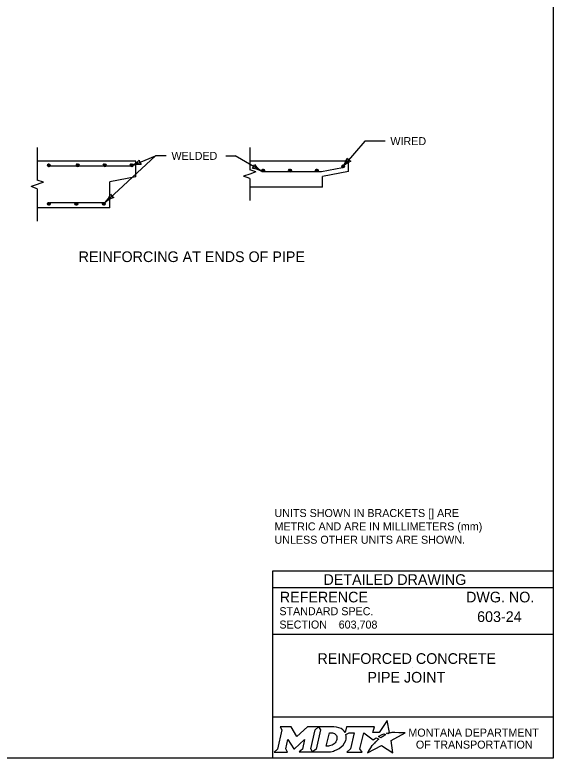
# Model space of a CAD drawing. Extents: x 49991.4 to 50021, y 49987.6 to 50011.4.
# Drawn here: x 50012.72 to 50016.75, y 49987.8 to 49993.37 of the extents above; entities that cross this region are included whole.
import ezdxf

# ---------------------------------------------------------------- set-up
doc = ezdxf.new("R2010")
doc.units = 0
for name, color, linetype in [('Default', 7, 'Continuous'), ('Level 1', 7, 'Continuous'), ('Level 2', 7, 'Continuous'), ('Level 3', 7, 'Continuous'), ('Level 5', 7, 'Continuous'), ('Level 6', 7, 'Continuous')]:
    doc.layers.add(name, color=color, linetype=linetype)

msp = doc.modelspace()

# ---------------------------------------------------------------- linework, layer by layer
at = {"layer": 'Default'}
for points in [[(50015.5126, 49987.9811), (50015.5023, 49987.9867), (50015.5139, 49987.9895), (50015.5255, 49987.9915), (50015.5081, 49988.0816), (50015.4486, 49987.9903), (50015.4013, 49987.9896), (50015.4116, 49988.0337), (50015.2024, 49988.0338), (50015.1923, 49987.9913), (50015.1865, 49987.9996)], [(50014.7056, 49988.0338), (50014.7197, 49988.0104), (50014.6862, 49987.8671), (50014.6605, 49987.8446), (50014.7621, 49987.8446), (50014.7486, 49987.8674), (50014.7648, 49987.9375), (50014.8085, 49987.8685), (50014.8138, 49987.8685), (50014.8889, 49987.938), (50014.8725, 49987.8669), (50014.8478, 49987.8449), (50014.9494, 49987.8449), (50014.9356, 49987.8682), (50014.9688, 49988.0106)], [(50014.9688, 49988.0106), (50014.9941, 49988.0338), (50014.9117, 49988.0338), (50014.8321, 49987.9608), (50014.7876, 49988.0335), (50014.7056, 49988.0338)], [(50015.1077, 49988.0338), (50014.9941, 49988.0338), (50015.0088, 49988.0109), (50014.9749, 49987.8671), (50014.9494, 49987.8449), (50015.06, 49987.8449)], [(50015.1317, 49987.9471), (50015.1305, 49987.939), (50015.1273, 49987.9297), (50015.1231, 49987.9215), (50015.1175, 49987.914), (50015.111, 49987.9071), (50015.1031, 49987.9008), (50015.0948, 49987.8961), (50015.0857, 49987.8922), (50015.0766, 49987.8899), (50015.0674, 49987.889), (50015.0515, 49987.889), (50015.0751, 49987.989), (50015.0911, 49987.989), (50015.0987, 49987.9884), (50015.1063, 49987.9865), (50015.1129, 49987.9835), (50015.119, 49987.9793), (50015.1238, 49987.9743), (50015.1275, 49987.9683), (50015.1302, 49987.9621), (50015.1318, 49987.9547), (50015.1318, 49987.9517), (50015.1317, 49987.9471)], [(50015.1991, 49987.9747), (50015.2237, 49987.9878), (50015.2606, 49987.9878), (50015.232, 49987.8673), (50015.2045, 49987.8446), (50015.3207, 49987.8446), (50015.3037, 49987.8675), (50015.3319, 49987.9877), (50015.4032, 49987.936), (50015.4243, 49987.9511), (50015.444, 49987.9402)], [(50015.3882, 49987.8843), (50015.3729, 49987.8599), (50015.3682, 49987.8524), (50015.3624, 49987.8438), (50015.3601, 49987.8395), (50015.4654, 49987.8926), (50015.5493, 49987.8375), (50015.5362, 49987.9302), (50015.6431, 49987.9886), (50015.5938, 49987.9894), (50015.5637, 49987.9898), (50015.5429, 49987.9901), (50015.5361, 49987.9886), (50015.5312, 49987.9874), (50015.5228, 49987.9851), (50015.5126, 49987.9811)], [(50015.4622, 49987.9535), (50015.4598, 49987.9518), (50015.4415, 49987.9614), (50015.4518, 49987.9671), (50015.4559, 49987.9693), (50015.4645, 49987.9733), (50015.4702, 49987.9759), (50015.4781, 49987.9789), (50015.4854, 49987.9816), (50015.4972, 49987.9742), (50015.4932, 49987.9721), (50015.4886, 49987.9696), (50015.4844, 49987.9674), (50015.4794, 49987.9645), (50015.4775, 49987.9634), (50015.4748, 49987.9618), (50015.4723, 49987.9604), (50015.47, 49987.9588), (50015.4674, 49987.957), (50015.4647, 49987.9552), (50015.4622, 49987.9535)], [(50015.4021, 49987.9004), (50015.4021, 49987.9004)], [(50015.1057, 49987.8522), (50015.1141, 49987.8548), (50015.1271, 49987.8602), (50015.1475, 49987.8712)]]:
    msp.add_lwpolyline(points, dxfattribs=at)
for centre, radius, start, end in [((50015.1308, 49987.9554), 0.0709, 339.5329, 15.8582), ((50015.0868, 49987.9727), 0.1183, 300.9103, 339.1383)]:
    msp.add_arc(centre, radius, start, end, dxfattribs=at)
for centre, major_axis, ratio, start_param, end_param in [((50015.1056, 49987.9864), (0.0834, -0.0037), 0.568097, 0.61298, 1.570796), ((50015.1612, 49987.9937), (0.0361, -0.0295), 0.469099, 1.225588, 1.570796), ((50015.4329, 49987.9305), (-0.0112, -0.0097), 0.021651, 3.157348, 6.283185), ((50015.3952, 49987.8923), (-0.00694, -0.00806), 0.008222, 0, 3.137361), ((50015.4119, 49987.9106), (-0.0098, -0.0102), 0.016458, 3.141593, 6.279097), ((50015.0603, 49987.9932), (0, 0.1484), 0.987302, 3.139398, 3.456847)]:
    msp.add_ellipse(centre, major_axis=major_axis, ratio=ratio, start_param=start_param, end_param=end_param, dxfattribs=at)
at = {"layer": 'Level 1'}
for p, q in [((50013.6268, 49992.2718), (50012.8876, 49992.2718)), ((50013.5877, 49992.2327), (50012.9814, 49992.2327)), ((50012.9814, 49992.2327), (50012.9814, 49992.2327)), ((50013.1834, 49992.2327), (50013.1834, 49992.2327)), ((50013.3856, 49992.2327), (50013.3856, 49992.2327)), ((50013.5877, 49992.2327), (50013.5877, 49992.2327)), ((50013.6268, 49992.1537), (50013.6268, 49992.2718)), ((50015.2179, 49992.2718), (50014.4786, 49992.2718)), ((50015.0148, 49992.1928), (50015.1719, 49992.2243)), ((50015.2179, 49992.1936), (50015.2179, 49992.2718)), ((50014.5724, 49992.1928), (50014.5724, 49992.1928)), ((50014.5724, 49992.1928), (50015.0148, 49992.1928)), ((50014.7733, 49992.1928), (50014.7733, 49992.1928)), ((50014.9742, 49992.1928), (50014.9742, 49992.1928)), ((50015.2179, 49992.1936), (50015.0225, 49992.1545)), ((50013.6268, 49992.1537), (50013.4314, 49992.1147)), ((50013.4314, 49991.92), (50013.4314, 49992.1147)), ((50015.0225, 49992.0764), (50015.0225, 49992.1545)), ((50015.0225, 49992.0764), (50014.4786, 49992.0764)), ((50013.3923, 49991.9591), (50012.9814, 49991.9591)), ((50012.9814, 49991.9591), (50012.9814, 49991.9591)), ((50013.1868, 49991.9591), (50013.1868, 49991.9591)), ((50013.3923, 49991.9591), (50013.3923, 49991.9591)), ((50013.4314, 49991.92), (50012.8876, 49991.92))]:
    msp.add_line(p, q, dxfattribs=at)
msp.add_lwpolyline([(49999.3835, 49998.9992), (50016.7501, 49998.9992), (50016.7501, 49987.7988), (49999.3835, 49987.7988)], close=True, dxfattribs=at)
for points in [[(50012.9635, 49992.2387), (50012.9746, 49992.2497)], [(50012.9636, 49992.2404), (50012.9729, 49992.2497)], [(50012.9638, 49992.2372), (50012.9761, 49992.2495)], [(50012.9639, 49992.2424), (50012.9709, 49992.2493)], [(50012.9642, 49992.236), (50012.9773, 49992.2491)], [(50012.9647, 49992.2348), (50012.9785, 49992.2486)], [(50012.9653, 49992.2338), (50012.9795, 49992.248)], [(50012.9657, 49992.2458), (50012.9675, 49992.2476), (50012.9676, 49992.2477)], [(50012.966, 49992.2328), (50012.966, 49992.2329), (50012.9804, 49992.2473), (50012.9805, 49992.2473)], [(50012.9668, 49992.232), (50012.9668, 49992.232), (50012.9813, 49992.2465), (50012.9813, 49992.2465)], [(50012.9678, 49992.2313), (50012.982, 49992.2455)], [(50012.9688, 49992.2306), (50012.9827, 49992.2445)], [(50012.9699, 49992.23), (50012.9832, 49992.2434)], [(50012.9711, 49992.2297), (50012.9836, 49992.2422)], [(50012.9725, 49992.2293), (50012.9839, 49992.2408)], [(50012.9742, 49992.2293), (50012.9839, 49992.2392)], [(50012.9761, 49992.2296), (50012.9837, 49992.2372)], [(50012.9787, 49992.2306), (50012.9827, 49992.2346)], [(50013.1801, 49992.2395), (50013.1911, 49992.2505)], [(50013.1802, 49992.2411), (50013.1895, 49992.2505)], [(50013.1803, 49992.238), (50013.1926, 49992.2503)], [(50013.1805, 49992.2432), (50013.1874, 49992.2501)], [(50013.1807, 49992.2368), (50013.1938, 49992.2499)], [(50013.1813, 49992.2356), (50013.195, 49992.2494)], [(50013.1819, 49992.2346), (50013.196, 49992.2488)], [(50013.1822, 49992.2465), (50013.184, 49992.2484), (50013.1841, 49992.2485)], [(50013.1825, 49992.2336), (50013.1826, 49992.2336), (50013.197, 49992.2481), (50013.197, 49992.2481)], [(50013.1834, 49992.2328), (50013.1834, 49992.2328), (50013.1978, 49992.2472), (50013.1978, 49992.2472)], [(50013.1843, 49992.2321), (50013.1985, 49992.2463)], [(50013.1853, 49992.2314), (50013.1992, 49992.2453)], [(50013.1864, 49992.2308), (50013.1998, 49992.2442)], [(50013.1877, 49992.2304), (50013.2002, 49992.2429)], [(50013.1891, 49992.2301), (50013.2004, 49992.2415)], [(50013.1907, 49992.2301), (50013.2005, 49992.24)], [(50013.1926, 49992.2304), (50013.2002, 49992.238)], [(50013.1952, 49992.2314), (50013.1992, 49992.2354)], [(50013.3822, 49992.2395), (50013.3932, 49992.2505)], [(50013.3823, 49992.2411), (50013.3916, 49992.2505)], [(50013.3825, 49992.238), (50013.3947, 49992.2503)], [(50013.3826, 49992.2432), (50013.3896, 49992.2501)], [(50013.3829, 49992.2368), (50013.396, 49992.2499)], [(50013.3834, 49992.2356), (50013.3972, 49992.2494)], [(50013.384, 49992.2346), (50013.3982, 49992.2488)], [(50013.3843, 49992.2465), (50013.3861, 49992.2484), (50013.3863, 49992.2485)], [(50013.3846, 49992.2336), (50013.3847, 49992.2336), (50013.3991, 49992.2481), (50013.3992, 49992.2481)], [(50013.3855, 49992.2328), (50013.3855, 49992.2328), (50013.4, 49992.2472), (50013.4, 49992.2472)], [(50013.3864, 49992.2321), (50013.4007, 49992.2463)], [(50013.3875, 49992.2314), (50013.4014, 49992.2453)], [(50013.3886, 49992.2308), (50013.4019, 49992.2442)], [(50013.3898, 49992.2304), (50013.4023, 49992.2429)], [(50013.3912, 49992.2301), (50013.4025, 49992.2415)], [(50013.3929, 49992.2301), (50013.4026, 49992.24)], [(50013.3947, 49992.2304), (50013.4024, 49992.238)], [(50013.3974, 49992.2314), (50013.4014, 49992.2354)], [(50013.5843, 49992.2395), (50013.5953, 49992.2505)], [(50013.5844, 49992.2411), (50013.5937, 49992.2505)], [(50013.5845, 49992.238), (50013.5968, 49992.2503)], [(50013.5847, 49992.2432), (50013.5916, 49992.2501)], [(50013.5849, 49992.2368), (50013.5981, 49992.2499)], [(50013.5855, 49992.2356), (50013.5992, 49992.2494)], [(50013.5861, 49992.2346), (50013.6002, 49992.2488)], [(50013.5864, 49992.2465), (50013.5882, 49992.2484), (50013.5884, 49992.2485)], [(50013.5867, 49992.2336), (50013.5868, 49992.2336), (50013.6012, 49992.2481), (50013.6013, 49992.2481)], [(50013.5876, 49992.2328), (50013.5876, 49992.2328), (50013.602, 49992.2472), (50013.602, 49992.2472)], [(50013.5885, 49992.2321), (50013.6027, 49992.2463)], [(50013.5895, 49992.2314), (50013.6034, 49992.2453)], [(50013.5906, 49992.2308), (50013.604, 49992.2442)], [(50013.5919, 49992.2304), (50013.6044, 49992.2429)], [(50013.5933, 49992.2301), (50013.6046, 49992.2415)], [(50013.5949, 49992.2301), (50013.6047, 49992.24)], [(50013.5968, 49992.2304), (50013.6045, 49992.238)], [(50013.5995, 49992.2314), (50013.6034, 49992.2354)], [(50015.1686, 49992.2327), (50015.1779, 49992.2421)], [(50015.1686, 49992.2311), (50015.1796, 49992.2421)], [(50015.1688, 49992.2296), (50015.1811, 49992.2418)], [(50015.169, 49992.2347), (50015.1759, 49992.2417)], [(50015.1692, 49992.2283), (50015.1823, 49992.2415)], [(50015.1697, 49992.2271), (50015.1835, 49992.241)], [(50015.1704, 49992.2261), (50015.1845, 49992.2404)], [(50015.1707, 49992.2381), (50015.1725, 49992.24), (50015.1726, 49992.24)], [(50015.171, 49992.2251), (50015.1711, 49992.2252), (50015.1855, 49992.2397), (50015.1855, 49992.2397)], [(50015.1718, 49992.2243), (50015.1718, 49992.2243), (50015.1863, 49992.2388), (50015.1863, 49992.2388)], [(50015.1728, 49992.2236), (50015.187, 49992.2379)], [(50015.1738, 49992.2229), (50015.1877, 49992.2368)], [(50015.1749, 49992.2224), (50015.1883, 49992.2357)], [(50015.1761, 49992.222), (50015.1887, 49992.2345)], [(50015.1776, 49992.2217), (50015.1889, 49992.2331)], [(50015.1792, 49992.2217), (50015.189, 49992.2315)], [(50015.1811, 49992.2219), (50015.1887, 49992.2296)], [(50015.1837, 49992.2229), (50015.1877, 49992.2269)], [(50014.5691, 49992.1996), (50014.5801, 49992.2107)], [(50014.5692, 49992.2013), (50014.5785, 49992.2107)], [(50014.5693, 49992.1981), (50014.5816, 49992.2104)], [(50014.5695, 49992.2033), (50014.5764, 49992.2103)], [(50014.5697, 49992.1969), (50014.5828, 49992.21)], [(50014.5703, 49992.1957), (50014.584, 49992.2096)], [(50014.5709, 49992.1947), (50014.585, 49992.2089)], [(50014.5712, 49992.2067), (50014.573, 49992.2085), (50014.5731, 49992.2086)], [(50014.5715, 49992.1937), (50014.5716, 49992.1938), (50014.586, 49992.2082), (50014.586, 49992.2082)], [(50014.5724, 49992.1929), (50014.5724, 49992.1929), (50014.5868, 49992.2074), (50014.5868, 49992.2074)], [(50014.5733, 49992.1922), (50014.5875, 49992.2064)], [(50014.5743, 49992.1915), (50014.5882, 49992.2054)], [(50014.5754, 49992.191), (50014.5888, 49992.2043)], [(50014.5767, 49992.1906), (50014.5892, 49992.2031)], [(50014.5781, 49992.1903), (50014.5894, 49992.2017)], [(50014.5797, 49992.1903), (50014.5895, 49992.2001)], [(50014.5816, 49992.1905), (50014.5892, 49992.1981)], [(50014.5842, 49992.1915), (50014.5882, 49992.1955)], [(50014.7699, 49992.1996), (50014.7809, 49992.2107)], [(50014.77, 49992.2013), (50014.7793, 49992.2107)], [(50014.7701, 49992.1981), (50014.7824, 49992.2104)], [(50014.7703, 49992.2033), (50014.7772, 49992.2103)], [(50014.7705, 49992.1969), (50014.7837, 49992.21)], [(50014.7711, 49992.1957), (50014.7848, 49992.2096)], [(50014.7717, 49992.1947), (50014.7858, 49992.2089)], [(50014.772, 49992.2067), (50014.7738, 49992.2085), (50014.774, 49992.2086)], [(50014.7723, 49992.1937), (50014.7724, 49992.1938), (50014.7868, 49992.2082), (50014.7869, 49992.2082)], [(50014.7732, 49992.1929), (50014.7732, 49992.1929), (50014.7876, 49992.2074), (50014.7876, 49992.2074)], [(50014.7741, 49992.1922), (50014.7883, 49992.2064)], [(50014.7751, 49992.1915), (50014.7891, 49992.2054)], [(50014.7762, 49992.191), (50014.7896, 49992.2043)], [(50014.7775, 49992.1906), (50014.79, 49992.2031)], [(50014.7789, 49992.1903), (50014.7902, 49992.2017)], [(50014.7805, 49992.1903), (50014.7903, 49992.2001)], [(50014.7824, 49992.1905), (50014.7901, 49992.1981)], [(50014.7851, 49992.1915), (50014.7891, 49992.1955)], [(50014.9708, 49992.1996), (50014.9818, 49992.2107)], [(50014.9709, 49992.2013), (50014.9802, 49992.2107)], [(50014.971, 49992.1981), (50014.9833, 49992.2104)], [(50014.9712, 49992.2033), (50014.9781, 49992.2103)], [(50014.9714, 49992.1969), (50014.9846, 49992.21)], [(50014.972, 49992.1957), (50014.9857, 49992.2096)], [(50014.9726, 49992.1947), (50014.9867, 49992.2089)], [(50014.9729, 49992.2067), (50014.9747, 49992.2085), (50014.9749, 49992.2086)], [(50014.9732, 49992.1937), (50014.9733, 49992.1938), (50014.9877, 49992.2082), (50014.9878, 49992.2082)], [(50014.9741, 49992.1929), (50014.9741, 49992.1929), (50014.9885, 49992.2074), (50014.9885, 49992.2074)], [(50014.975, 49992.1922), (50014.9892, 49992.2064)], [(50014.976, 49992.1915), (50014.9899, 49992.2054)], [(50014.9771, 49992.191), (50014.9905, 49992.2043)], [(50014.9784, 49992.1906), (50014.9909, 49992.2031)], [(50014.9798, 49992.1903), (50014.9911, 49992.2017)], [(50014.9814, 49992.1903), (50014.9912, 49992.2001)], [(50014.9833, 49992.1905), (50014.991, 49992.1981)], [(50014.986, 49992.1915), (50014.9899, 49992.1955)], [(50012.9643, 49991.9507), (50012.9754, 49991.9617)], [(50012.9644, 49991.9523), (50012.9737, 49991.9617)], [(50012.9646, 49991.9492), (50012.9768, 49991.9614)], [(50012.9647, 49991.9543), (50012.9717, 49991.9613)], [(50012.965, 49991.9479), (50012.9781, 49991.9611)], [(50012.9655, 49991.9468), (50012.9793, 49991.9606)], [(50012.9661, 49991.9457), (50012.9803, 49991.96)], [(50012.9664, 49991.9577), (50012.9682, 49991.9596), (50012.9684, 49991.9597)], [(50012.9668, 49991.9447), (50012.9668, 49991.9448), (50012.9812, 49991.9593), (50012.9813, 49991.9593)], [(50012.9676, 49991.9439), (50012.9676, 49991.9439), (50012.9821, 49991.9584), (50012.9821, 49991.9584)], [(50012.9685, 49991.9432), (50012.9828, 49991.9575)], [(50012.9696, 49991.9425), (50012.9835, 49991.9564)], [(50012.9707, 49991.942), (50012.984, 49991.9554)], [(50012.9719, 49991.9416), (50012.9844, 49991.9541)], [(50012.9733, 49991.9413), (50012.9847, 49991.9527)], [(50012.975, 49991.9413), (50012.9847, 49991.9511)], [(50012.9768, 49991.9415), (50012.9845, 49991.9492)], [(50012.9795, 49991.9425), (50012.9835, 49991.9465)], [(50013.1698, 49991.9523), (50013.1791, 49991.9617)], [(50013.1698, 49991.9507), (50013.1808, 49991.9617)], [(50013.17, 49991.9492), (50013.1823, 49991.9614)], [(50013.1702, 49991.9543), (50013.1771, 49991.9613)], [(50013.1704, 49991.9479), (50013.1835, 49991.9611)], [(50013.1709, 49991.9468), (50013.1847, 49991.9606)], [(50013.1716, 49991.9457), (50013.1857, 49991.96)], [(50013.1719, 49991.9577), (50013.1737, 49991.9596), (50013.1738, 49991.9597)], [(50013.1722, 49991.9447), (50013.1723, 49991.9448), (50013.1866, 49991.9593), (50013.1867, 49991.9593)], [(50013.173, 49991.9439), (50013.173, 49991.9439), (50013.1875, 49991.9584), (50013.1875, 49991.9584)], [(50013.174, 49991.9432), (50013.1882, 49991.9575)], [(50013.175, 49991.9425), (50013.1889, 49991.9564)], [(50013.1761, 49991.942), (50013.1895, 49991.9554)], [(50013.1773, 49991.9416), (50013.1898, 49991.9541)], [(50013.1787, 49991.9413), (50013.1901, 49991.9527)], [(50013.1804, 49991.9413), (50013.1902, 49991.9511)], [(50013.1823, 49991.9415), (50013.1899, 49991.9492)], [(50013.1849, 49991.9425), (50013.1889, 49991.9465)], [(50013.3753, 49991.9523), (50013.3846, 49991.9617)], [(50013.3753, 49991.9507), (50013.3863, 49991.9617)], [(50013.3755, 49991.9492), (50013.3878, 49991.9614)], [(50013.3757, 49991.9543), (50013.3826, 49991.9613)], [(50013.3759, 49991.9479), (50013.389, 49991.9611)], [(50013.3764, 49991.9468), (50013.3902, 49991.9606)], [(50013.3771, 49991.9457), (50013.3912, 49991.96)], [(50013.3774, 49991.9577), (50013.3792, 49991.9596), (50013.3793, 49991.9597)], [(50013.3777, 49991.9447), (50013.3778, 49991.9448), (50013.3922, 49991.9593), (50013.3922, 49991.9593)], [(50013.3786, 49991.9439), (50013.3786, 49991.9439), (50013.393, 49991.9584), (50013.393, 49991.9584)], [(50013.3795, 49991.9432), (50013.3937, 49991.9575)], [(50013.3805, 49991.9425), (50013.3944, 49991.9564)], [(50013.3816, 49991.942), (50013.395, 49991.9554)], [(50013.3829, 49991.9416), (50013.3954, 49991.9541)], [(50013.3843, 49991.9413), (50013.3956, 49991.9527)], [(50013.3859, 49991.9413), (50013.3957, 49991.9511)], [(50013.3878, 49991.9415), (50013.3954, 49991.9492)], [(50013.3904, 49991.9425), (50013.3944, 49991.9465)]]:
    msp.add_lwpolyline(points, dxfattribs=at)
for centre in [(50012.9738, 49992.2396), (50013.1903, 49992.2403), (50013.3924, 49992.2403), (50013.5945, 49992.2403), (50015.1788, 49992.2319), (50014.5793, 49992.2005), (50014.7801, 49992.2005), (50014.981, 49992.2005), (50012.9745, 49991.9515), (50013.18, 49991.9515), (50013.3855, 49991.9515)]:
    msp.add_circle(centre, 0.0102, dxfattribs=at)
at = {"layer": 'Level 3'}
for p, q in [((50015.3404, 49992.4206), (50015.1852, 49992.2399)), ((50015.4917, 49992.4206), (50015.3404, 49992.4206)), ((50013.3923, 49991.9591), (50013.7731, 49992.3104)), ((50013.5877, 49992.2327), (50013.7731, 49992.3104)), ((50013.8525, 49992.3104), (50013.7731, 49992.3104)), ((50014.3006, 49992.3104), (50014.3693, 49992.3104)), ((50014.5724, 49992.1929), (50014.3693, 49992.3104))]:
    msp.add_line(p, q, dxfattribs=at)
for centre, radius, start, end in [((50014.9878, 49992.3672), 0.233, 322.1852, 341.435), ((50015.2554, 49992.3216), 0.0548, 211.4967, 247.219), ((50013.4872, 49992.4429), 0.233, 295.5656, 314.8154), ((50013.6651, 49992.0243), 0.2223, 90.1943, 110.3778), ((50013.706, 49992.2823), 0.0548, 184.8771, 220.5994), ((50014.4614, 49992.2571), 0.0548, 312.088, 347.8104), ((50014.6916, 49992.3806), 0.2223, 217.4052, 237.5887), ((50015.3345, 49992.0727), 0.2223, 116.8139, 136.9974), ((50014.4658, 49991.9857), 0.233, 62.7765, 82.0264), ((50013.2261, 49992.1224), 0.233, 315.5198, 334.7697), ((50013.4866, 49992.0461), 0.0548, 204.8313, 240.5537), ((50013.5362, 49991.7897), 0.2223, 110.1485, 130.332)]:
    msp.add_arc(centre, radius, start, end, dxfattribs=at)
at = {"layer": 'Level 5'}
for p, q in [((50016.7501, 49989.1988), (50014.6501, 49989.1988)), ((50014.6501, 49989.1988), (50014.6501, 49987.7988)), ((50016.7501, 49989.0738), (50014.6501, 49989.0738)), ((50016.3862, 49988.8587), (50016.3862, 49988.8587)), ((50015.1444, 49988.7993), (50015.1444, 49988.7993)), ((50016.7501, 49988.7238), (50014.6501, 49988.7238)), ((50015.7001, 49988.4747), (50015.7001, 49988.4747)), ((50016.7501, 49988.1057), (50014.6501, 49988.1057))]:
    msp.add_line(p, q, dxfattribs=at)
at = {"layer": 'Level 6'}
for p, q in [((50012.8876, 49992.3718), (50012.8876, 49992.1283)), ((50014.4786, 49992.3718), (50014.4786, 49992.2065)), ((50014.4786, 49992.1741), (50014.4329, 49992.1579)), ((50014.5243, 49992.1903), (50014.4786, 49992.2065)), ((50014.5243, 49992.1903), (50014.4786, 49992.1741)), ((50012.9333, 49992.1121), (50012.8876, 49992.1283)), ((50012.9333, 49992.1121), (50012.8876, 49992.0959)), ((50014.4786, 49992.1417), (50014.4329, 49992.1579)), ((50014.4786, 49992.1417), (50014.4786, 49991.9764)), ((50012.8876, 49992.0959), (50012.8419, 49992.0797)), ((50012.8876, 49992.0635), (50012.8419, 49992.0797)), ((50012.8876, 49992.0635), (50012.8876, 49991.82))]:
    msp.add_line(p, q, dxfattribs=at)

# ---------------------------------------------------------------- texts
at = {"layer": 'Default'}
for s, p in [('MONTANA DEPARTMENT', (50015.6663, 49987.96)), ('OF TRANSPORTATION', (50015.7225, 49987.87))]:
    msp.add_text(s, height=0.06, dxfattribs=at).set_placement(p)
at = {"layer": 'Level 2'}
for s, height, p in [('WIRED', 0.06, (50015.5317, 49992.3906)), ('WELDED', 0.06, (50013.8925, 49992.2804)), ('REINFORCING AT ENDS OF PIPE', 0.08, (50013.1974, 49991.5148)), ('UNITS SHOWN IN BRACKETS [] ARE ', 0.06, (50014.6639, 49989.6048)), ('METRIC AND ARE IN MILLIMETERS (mm) ', 0.06, (50014.6639, 49989.5048)), ('UNLESS OTHER UNITS ARE SHOWN.', 0.06, (50014.6639, 49989.4048)), ('603-24', 0.08, (50016.1811, 49988.8187)), ('603,708', 0.06, (50015.1444, 49988.7693)), ('REINFORCED CONCRETE', 0.08, (50014.9855, 49988.5047)), ('PIPE JOINT', 0.08, (50015.3598, 49988.3647))]:
    msp.add_text(s, height=height, dxfattribs=at).set_placement(p)
at = {"layer": 'Level 5'}
for s, height, p in [('DETAILED DRAWING', 0.0799, (50015.0311, 49989.0963)), ('REFERENCE', 0.08, (50014.7037, 49988.9654)), ('DWG. NO.', 0.08, (50016.0979, 49988.9654)), ('STANDARD SPEC.', 0.06, (50014.7004, 49988.8694)), ('SECTION', 0.06, (50014.7004, 49988.7694))]:
    msp.add_text(s, height=height, dxfattribs=at).set_placement(p)

doc.saveas('drawing.dxf')
